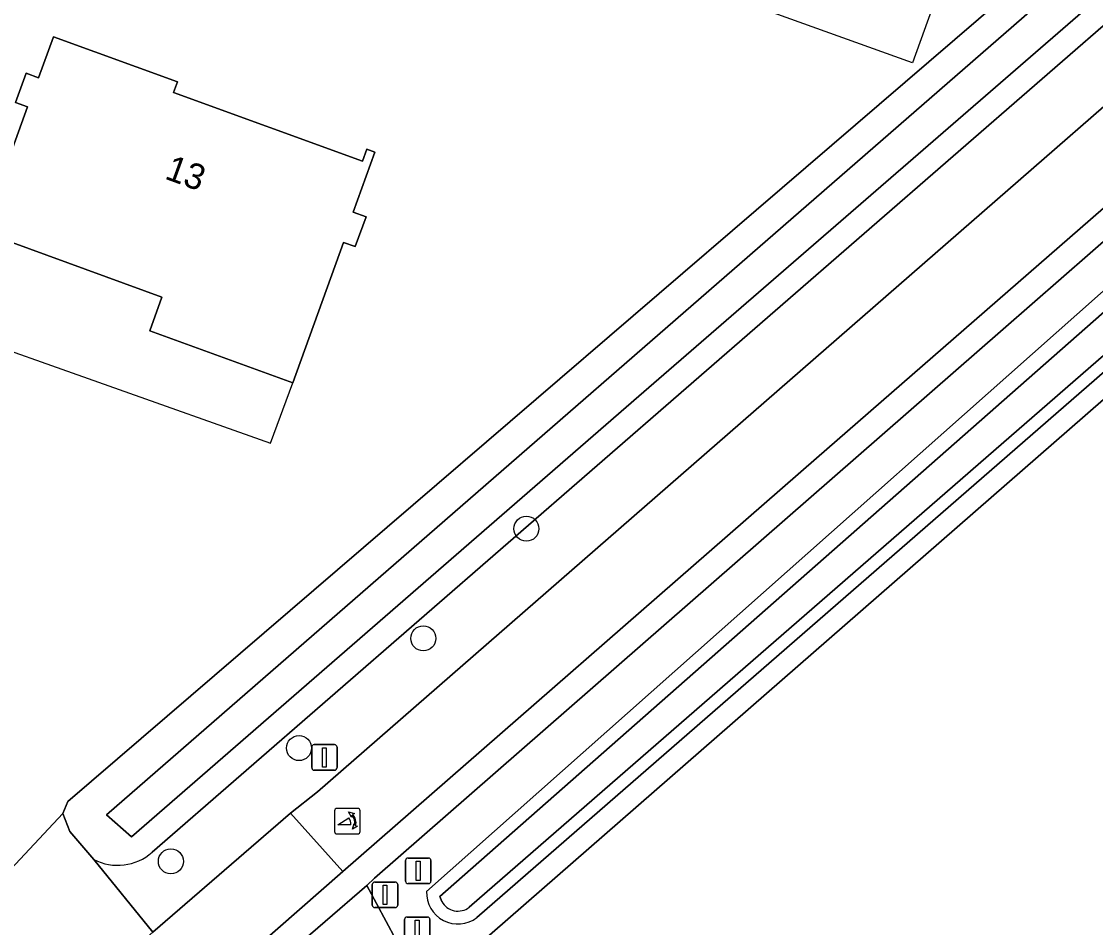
# Model space of a CAD drawing. Extents: x 163266 to 164362, y 381528 to 382286.
# Drawn here: x 163844.41 to 163886.36, y 381775.16 to 381810.55 of the extents above; entities that cross this region are included whole.
import ezdxf

# ---------------------------------------------------------------- set-up
doc = ezdxf.new("R2010")
doc.units = 0
for name, color, linetype in [('IMGEO_Afsluitpaal', 7, 'Continuous'), ('IMGEO_Boom', 7, 'Continuous'), ('IMGEO_Erf', 7, 'Continuous'), ('IMGEO_Groenvoorziening', 7, 'Continuous'), ('IMGEO_Hek', 7, 'Continuous'), ('IMGEO_Oever', 7, 'Continuous'), ('IMGEO_Pand', 7, 'Continuous'), ('IMGEO_Pand_nummerreeks', 7, 'Continuous'), ('IMGEO_Pand_overbouw', 7, 'Continuous'), ('IMGEO_Pand_vergunning_verleend', 7, 'Continuous'), ('IMGEO_Poller', 7, 'Continuous'), ('IMGEO_Rijbaan_lokaal_gesloten', 7, 'Continuous'), ('IMGEO_Verkeersbordpaal', 7, 'Continuous'), ('IMGEO_Voetpad_gesloten', 7, 'Continuous'), ('IMGEO_Voetpad_open', 7, 'Continuous'), ('IMGEO_Waterloop', 7, 'Continuous')]:
    doc.layers.add(name, color=color, linetype=linetype)

msp = doc.modelspace()

# ---------------------------------------------------------------- linework, layer by layer
at = {"layer": 'IMGEO_Afsluitpaal'}
for p, q in [((163858.11, 381776.042), (163858.11, 381776.842)), ((163858.11, 381776.842), (163858.11, 381776.042)), ((163858.21, 381776.942), (163859, 381776.942)), ((163859, 381776.942), (163858.21, 381776.942)), ((163859.1, 381776.842), (163859.1, 381776.042)), ((163859.1, 381776.042), (163859.1, 381776.842)), ((163859, 381775.942), (163858.21, 381775.942)), ((163858.21, 381775.942), (163859, 381775.942)), ((163859.369, 381774.673), (163859.369, 381775.473)), ((163859.369, 381775.473), (163859.369, 381774.673)), ((163859.469, 381775.573), (163860.259, 381775.573)), ((163860.259, 381775.573), (163859.469, 381775.573)), ((163860.359, 381775.473), (163860.359, 381774.673)), ((163860.359, 381774.673), (163860.359, 381775.473))]:
    msp.add_line(p, q, dxfattribs=at)
for points in [[(163858.53, 381776.817), (163858.68, 381776.817), (163858.68, 381776.067), (163858.53, 381776.067), (163858.53, 381776.817)], [(163859.789, 381775.448), (163859.939, 381775.448), (163859.939, 381774.698), (163859.789, 381774.698), (163859.789, 381775.448)]]:
    msp.add_lwpolyline(points, dxfattribs=at)
for centre, start, end in [((163858.21, 381776.842), 90, 180), ((163858.21, 381776.842), 90, 180), ((163859, 381776.842), 0, 90), ((163859, 381776.842), 360, 90), ((163858.21, 381776.042), 180, 270), ((163858.21, 381776.042), 180, 270), ((163859, 381776.042), 270, 0), ((163859, 381776.042), 270, 0), ((163859.469, 381775.473), 90, 180), ((163859.469, 381775.473), 90, 180), ((163860.259, 381775.473), 0, 90), ((163860.259, 381775.473), 360, 90)]:
    msp.add_arc(centre, 0.1, start, end, dxfattribs=at)
at = {"layer": 'IMGEO_Boom'}
for centre in [(163864.128, 381790.738), (163860.102, 381786.457), (163855.247, 381782.172), (163850.24, 381777.748)]:
    msp.add_circle(centre, 0.489, dxfattribs=at)
at = {"layer": 'IMGEO_Erf'}
for points in [[(163870.142, 381820.239), (163868.584, 381818.998), (163862.223, 381814.784), (163844.697, 381820.821), (163841.425, 381821.949), (163840.49, 381819.175), (163843.72, 381818.001), (163840.476, 381809.078), (163837.246, 381810.252), (163825.558, 381776.861), (163838.968, 381772.083), (163846.023, 381779.611), (163846.214, 381780.09), (163981.759, 381896.51)], [(163923.226, 381827.395), (163896.672, 381804.504), (163862.173, 381774.429)]]:
    msp.add_lwpolyline(points, dxfattribs=at)
msp.add_lwpolyline([(163850.495, 381808.192), (163850.341, 381807.769), (163857.72, 381805.087), (163857.893, 381805.563), (163858.214, 381805.446), (163857.362, 381803.102), (163857.863, 381802.92), (163857.44, 381801.757), (163856.99, 381801.921), (163854.999, 381796.441), (163849.415, 381798.471), (163849.891, 381799.782), (163843.214, 381802.209), (163842.728, 381800.873), (163842.386, 381800.997), (163844.643, 381807.207), (163844.173, 381807.378), (163844.59, 381808.526), (163845.076, 381808.349), (163845.658, 381809.949)], close=True, dxfattribs=at)
at = {"layer": 'IMGEO_Groenvoorziening'}
for points in [[(163847.227, 381777.818), (163849.537, 381774.989), (163854.909, 381779.633), (163855.968, 381780.463), (164037.528, 381938.674)], [(163983.01, 381895.079), (163925.999, 381844.559), (163849.507, 381778.101)], [(163921.298, 381832.097), (163896.19, 381810.176), (163894.083, 381808.419), (163882.756, 381798.536), (163858.2, 381777.096), (163857.894, 381776.812), (163857.898, 381776.804), (163859.789, 381773.295), (163860.337, 381772.829), (163862.173, 381774.429), (163896.672, 381804.504), (163923.226, 381827.395), (163923.335, 381827.493), (163924.672, 381828.696), (163923.842, 381829.634), (163924.408, 381830.177)], [(163860.227, 381776.574), (163897.065, 381809.245), (163920.52, 381829.655)], [(163922.389, 381827.909), (163896.621, 381805.495), (163862.196, 381775.551)]]:
    msp.add_lwpolyline(points, dxfattribs=at)
msp.add_lwpolyline([(163849.537, 381774.989), (163847.227, 381777.818), (163846.291, 381778.92), (163846.023, 381779.611), (163838.968, 381772.083), (163843.096, 381770.612), (163844.113, 381770.197), (163845.182, 381771.143), (163846.052, 381771.894)], close=True, dxfattribs=at)
for centre, radius, start, end in [((163848.159, 381779.638), 2.044, 242.8892, 311.2618), ((163861.457, 381776.535), 1.231, 178.1975, 306.8939)]:
    msp.add_arc(centre, radius, start, end, dxfattribs=at)
at = {"layer": 'IMGEO_Hek'}
msp.add_lwpolyline([(163862.173, 381774.429), (163896.672, 381804.504)], dxfattribs=at)
at = {"layer": 'IMGEO_Oever'}
for points in [[(163981.759, 381896.51), (163846.214, 381780.09), (163846.023, 381779.611), (163846.291, 381778.92), (163847.227, 381777.818)], [(163849.507, 381778.101), (163925.999, 381844.559)], [(163920.52, 381829.655), (163897.065, 381809.245), (163860.227, 381776.574)], [(163860.821, 381776.182), (163860.753, 381776.371), (163920.794, 381829.23)], [(163921.967, 381828.204), (163911.76, 381819.327), (163881.482, 381792.989), (163861.898, 381775.954)], [(163862.196, 381775.551), (163896.621, 381805.495)]]:
    msp.add_lwpolyline(points, dxfattribs=at)
msp.add_lwpolyline([(163847.72, 381779.562), (163886.075, 381812.927), (163966.733, 381882.81), (163982.009, 381895.995), (163982.54, 381895.485), (163961.351, 381876.844), (163945.937, 381863.256), (163926.786, 381846.398), (163868.527, 381795.91), (163848.697, 381778.712)], close=True, dxfattribs=at)
for centre, radius, start, end in [((163848.159, 381779.638), 2.044, 242.8892, 311.2618), ((163861.457, 381776.535), 1.231, 178.1975, 306.8939), ((163861.458, 381776.534), 0.728, 208.8936, 307.2004)]:
    msp.add_arc(centre, radius, start, end, dxfattribs=at)
at = {"layer": 'IMGEO_Pand'}
msp.add_lwpolyline([(163854.999, 381796.441), (163856.99, 381801.921), (163857.44, 381801.757), (163857.863, 381802.92), (163857.362, 381803.102), (163858.214, 381805.446), (163857.893, 381805.563), (163857.72, 381805.087), (163850.341, 381807.769), (163850.495, 381808.192), (163845.658, 381809.949), (163845.076, 381808.349), (163844.59, 381808.526), (163844.173, 381807.378), (163844.643, 381807.207), (163842.386, 381800.997), (163842.728, 381800.873), (163843.214, 381802.209), (163849.891, 381799.782), (163849.415, 381798.471)], close=True, dxfattribs=at)
at = {"layer": 'IMGEO_Pand_overbouw'}
msp.add_lwpolyline([(163842.386, 381800.997), (163841.483, 381798.56), (163854.131, 381794.08), (163854.999, 381796.441), (163849.415, 381798.471), (163849.891, 381799.782), (163843.214, 381802.209), (163842.728, 381800.873)], close=True, dxfattribs=at)
at = {"layer": 'IMGEO_Pand_vergunning_verleend'}
msp.add_lwpolyline([(163870.536, 381812.053), (163872.815, 381818.383), (163881.492, 381815.259), (163879.214, 381808.929)], close=True, dxfattribs=at)
at = {"layer": 'IMGEO_Poller'}
for p, q in [((163856.636, 381779.722), (163856.636, 381778.915)), ((163856.636, 381779.722), (163856.636, 381778.915)), ((163857.538, 381779.817), (163856.73, 381779.817)), ((163857.538, 381779.817), (163856.73, 381779.817)), ((163857.632, 381778.915), (163857.632, 381779.722)), ((163857.632, 381778.915), (163857.632, 381779.722)), ((163856.73, 381778.82), (163857.538, 381778.82)), ((163856.73, 381778.82), (163857.538, 381778.82))]:
    msp.add_line(p, q, dxfattribs=at)
for points in [[(163857.315, 381779.546), (163857.303, 381779.473), (163857.178, 381779.678)], [(163857.178, 381779.678), (163857.409, 381779.612), (163857.338, 381779.58)], [(163857.271, 381779.173), (163856.758, 381779.173), (163857.188, 381779.448)], [(163857.331, 381779.001), (163857.397, 381779.232), (163857.427, 381779.164)], [(163857.463, 381779.137), (163857.535, 381779.126), (163857.331, 381779.001)]]:
    msp.add_lwpolyline(points, dxfattribs=at)
for centre, radius, start, end in [((163856.73, 381779.722), 0.0946, 90, 180), ((163856.73, 381779.722), 0.0946, 90, 180), ((163857.538, 381779.722), 0.0946, 0, 90), ((163857.538, 381779.722), 0.0946, 0, 90), ((163856.943, 381779.223), 0.332, 351.3247, 42.4854), ((163856.957, 381779.233), 0.476, 351.7527, 41.1691), ((163856.957, 381779.233), 0.516, 349.3569, 42.2912), ((163856.73, 381778.915), 0.0946, 180, 270), ((163856.73, 381778.915), 0.0946, 180, 270), ((163857.538, 381778.915), 0.0946, 270, 0), ((163857.538, 381778.915), 0.0946, 270, 0)]:
    msp.add_arc(centre, radius, start, end, dxfattribs=at)
at = {"layer": 'IMGEO_Rijbaan_lokaal_gesloten'}
msp.add_lwpolyline([(163994.123, 381896.877), (164001.88, 381903.643), (164037.55, 381934.629), (164049.758, 381945.234), (164051.471, 381946.521), (164055.13, 381949.211), (164052.722, 381952.074), (164050.939, 381950.414), (164050.865, 381950.343), (164048.125, 381947.909), (164037.528, 381938.674), (163855.968, 381780.463), (163854.909, 381779.633), (163856.952, 381777.354), (163875.466, 381793.487), (163918.881, 381831.318), (163926.223, 381837.754)], close=True, dxfattribs=at)
msp.add_lwpolyline([(163850.426, 381771.322), (163851.883, 381772.907), (163856.953, 381777.353), (163856.952, 381777.354), (163854.909, 381779.633), (163849.537, 381774.989), (163846.052, 381771.894), (163845.182, 381771.143)], dxfattribs=at)
at = {"layer": 'IMGEO_Verkeersbordpaal'}
for p, q in [((163855.742, 381781.407), (163855.742, 381782.207)), ((163855.742, 381782.207), (163855.742, 381781.407)), ((163855.842, 381782.307), (163856.632, 381782.307)), ((163856.632, 381782.307), (163855.842, 381782.307)), ((163856.732, 381782.207), (163856.732, 381781.407)), ((163856.732, 381781.407), (163856.732, 381782.207)), ((163856.632, 381781.307), (163855.842, 381781.307)), ((163855.842, 381781.307), (163856.632, 381781.307)), ((163859.409, 381776.979), (163859.409, 381777.779)), ((163859.409, 381777.779), (163859.409, 381776.979)), ((163859.509, 381777.879), (163860.299, 381777.879)), ((163860.299, 381777.879), (163859.509, 381777.879)), ((163860.399, 381777.779), (163860.399, 381776.979)), ((163860.399, 381776.979), (163860.399, 381777.779)), ((163860.299, 381776.879), (163859.509, 381776.879)), ((163859.509, 381776.879), (163860.299, 381776.879))]:
    msp.add_line(p, q, dxfattribs=at)
for points in [[(163856.162, 381782.182), (163856.312, 381782.182), (163856.312, 381781.432), (163856.162, 381781.432), (163856.162, 381782.182)], [(163859.829, 381777.754), (163859.979, 381777.754), (163859.979, 381777.004), (163859.829, 381777.004), (163859.829, 381777.754)]]:
    msp.add_lwpolyline(points, dxfattribs=at)
for centre, start, end in [((163855.842, 381782.207), 90, 180), ((163855.842, 381782.207), 90, 180), ((163856.632, 381782.207), 0, 90), ((163856.632, 381782.207), 360, 90), ((163855.842, 381781.407), 180, 270), ((163855.842, 381781.407), 180, 270), ((163856.632, 381781.407), 270, 0), ((163856.632, 381781.407), 270, 0), ((163859.509, 381777.779), 90, 180), ((163859.509, 381777.779), 90, 180), ((163860.299, 381777.779), 0, 90), ((163860.299, 381777.779), 360, 90), ((163859.509, 381776.979), 180, 270), ((163859.509, 381776.979), 180, 270), ((163860.299, 381776.979), 270, 0), ((163860.299, 381776.979), 270, 0)]:
    msp.add_arc(centre, 0.1, start, end, dxfattribs=at)
at = {"layer": 'IMGEO_Voetpad_gesloten'}
msp.add_lwpolyline([(163860.337, 381772.829), (163859.789, 381773.295), (163857.898, 381776.804), (163857.894, 381776.812), (163853.009, 381772.583), (163852.519, 381772.14), (163852.069, 381771.657), (163855.866, 381769.846), (163856.492, 381769.479), (163861.287, 381765.379), (163865.748, 381761.621), (163866.095, 381761.997), (163866.304, 381761.811), (163868.867, 381764.841), (163868.602, 381765.074), (163868.981, 381765.478)], close=True, dxfattribs=at)
at = {"layer": 'IMGEO_Voetpad_open'}
for points in [[(163918.881, 381831.318), (163875.466, 381793.487), (163856.952, 381777.354), (163856.953, 381777.353), (163851.883, 381772.907), (163850.426, 381771.322)], [(163849.572, 381768.615), (163850.5, 381769.785), (163852.069, 381771.657), (163852.519, 381772.14), (163853.009, 381772.583), (163857.894, 381776.812), (163858.2, 381777.096), (163882.756, 381798.536), (163894.083, 381808.419)]]:
    msp.add_lwpolyline(points, dxfattribs=at)
at = {"layer": 'IMGEO_Waterloop'}
msp.add_lwpolyline([(163847.72, 381779.562), (163848.697, 381778.712), (163868.527, 381795.91), (163926.786, 381846.398), (163945.937, 381863.256), (163961.351, 381876.844), (163982.54, 381895.485), (163982.009, 381895.995), (163966.733, 381882.81), (163886.075, 381812.927)], close=True, dxfattribs=at)
for points in [[(163920.794, 381829.23), (163860.753, 381776.371), (163860.821, 381776.182)], [(163861.898, 381775.954), (163881.482, 381792.989), (163911.76, 381819.327), (163921.967, 381828.204)]]:
    msp.add_lwpolyline(points, dxfattribs=at)
msp.add_arc((163861.458, 381776.534), 0.728, 208.8936, 307.2004, dxfattribs=at)

# ---------------------------------------------------------------- texts
at = {"layer": 'IMGEO_Pand_nummerreeks'}
msp.add_text('13', height=1, rotation=340.0256, dxfattribs=at).set_placement((163849.961, 381804.417))

doc.saveas('drawing.dxf')
